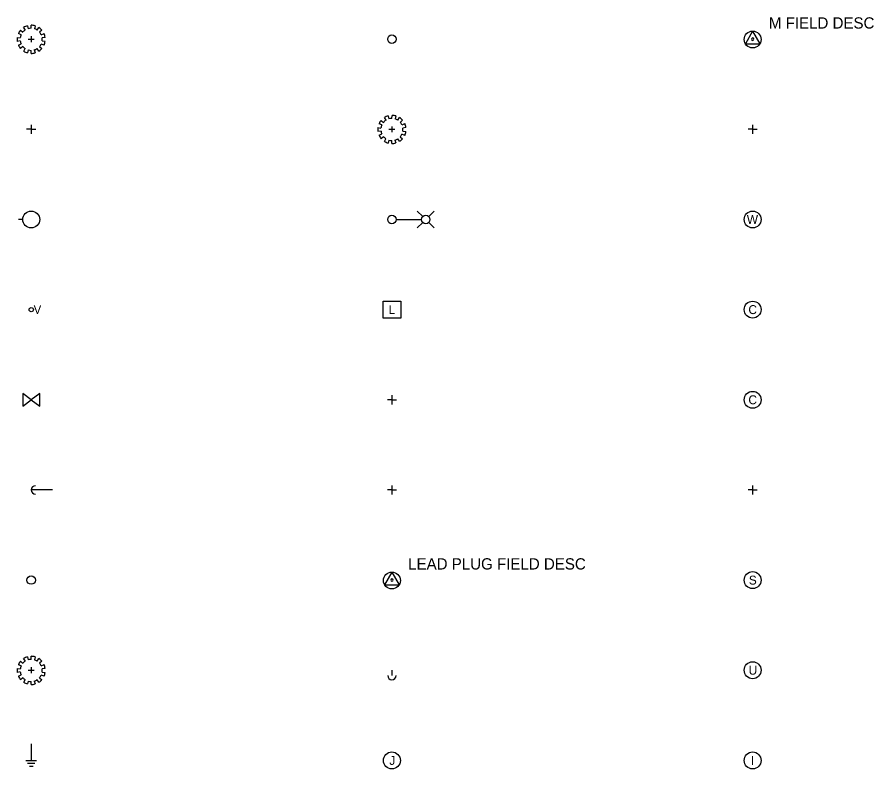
# Model space of a CAD drawing. Extents: x 91 to 2906, y -24 to 912.
# Drawn here: x 892.2 to 1367.2, y 495.3 to 912.2 of the extents above; entities that cross this region are included whole.
import ezdxf

# ---------------------------------------------------------------- set-up
doc = ezdxf.new("R2010")
doc.units = 0
for name, color, linetype in [('V-AFLD-DEVC', 7, 'Continuous'), ('V-COMM-MHOL', 7, 'Continuous'), ('V-FUEL-DEVC', 7, 'Continuous'), ('V-FUEL-VALT', 7, 'Continuous'), ('V-HTCW-JBOX', 7, 'Continuous'), ('V-INDW-JBOX', 7, 'Continuous'), ('V-POWR-POLE', 7, 'Continuous'), ('V-POWR-POLE-GUYS', 7, 'Continuous'), ('V-ROAD-SIGN', 7, 'Continuous'), ('V-SITE-OTLN', 7, 'Continuous'), ('V-SITE-VEGE', 7, 'Continuous'), ('V-SSWR-DEVC', 7, 'Continuous'), ('V-SSWR-JBOX', 7, 'Continuous'), ('V-SURV-DATA', 7, 'Continuous'), ('V-UTIL-DEVC', 7, 'Continuous'), ('V-UTIL-JBOX', 7, 'Continuous'), ('V-UTIL-MHOL', 7, 'Continuous'), ('V-WATR-DEVC', 7, 'Continuous'), ('V-WATR-VALT', 7, 'Continuous')]:
    doc.layers.add(name, color=color, linetype=linetype)

msp = doc.modelspace()

# ---------------------------------------------------------------- linework, layer by layer
at = {"layer": 'V-AFLD-DEVC'}
for p, q in [((900, 509.27), (900, 500)), ((896.98, 500), (903.02, 500)), ((897.98, 498.39), (902.02, 498.39)), ((898.99, 496.77), (901.01, 496.77))]:
    msp.add_line(p, q, dxfattribs=at)
at = {"layer": 'V-COMM-MHOL'}
for centre in [(1300, 750), (1300, 700)]:
    msp.add_circle(centre, 4.69, dxfattribs=at)
at = {"layer": 'V-FUEL-DEVC'}
msp.add_circle((900.02, 750), 1.17, dxfattribs=at)
at = {"layer": 'V-FUEL-VALT'}
for p, q in [((900, 700), (895.32, 703.53)), ((895.32, 703.53), (895.32, 696.47)), ((904.69, 703.52), (900, 700)), ((904.69, 696.48), (904.69, 703.52)), ((895.32, 696.47), (900, 700)), ((900, 700), (904.69, 696.48))]:
    msp.add_line(p, q, dxfattribs=at)
at = {"layer": 'V-HTCW-JBOX'}
for p, q in [((1300, 652.55), (1300, 647.46)), ((1300, 650), (1297.46, 650)), ((1300, 650), (1302.55, 650))]:
    msp.add_line(p, q, dxfattribs=at)
at = {"layer": 'V-INDW-JBOX'}
msp.add_circle((1300, 500), 4.69, dxfattribs=at)
at = {"layer": 'V-POWR-POLE'}
msp.add_circle((1100, 900), 2.34, dxfattribs=at)
at = {"layer": 'V-POWR-POLE-GUYS'}
msp.add_line((911.72, 650), (900, 650), dxfattribs=at)
msp.add_circle((900, 600), 2.34, dxfattribs=at)
msp.add_arc((902.34, 650), 2.34, 90, 270, dxfattribs=at)
at = {"layer": 'V-ROAD-SIGN'}
for p, q in [((1300, 852.55), (1300, 847.46)), ((1300, 850), (1297.46, 850)), ((1300, 850), (1302.55, 850))]:
    msp.add_line(p, q, dxfattribs=at)
at = {"layer": 'V-SITE-OTLN'}
for p, q in [((900, 852.55), (900, 847.46)), ((900, 850), (897.46, 850)), ((900, 850), (902.55, 850)), ((1117.09, 801.66), (1114.06, 804.69)), ((1120.41, 801.66), (1123.44, 804.69)), ((1102.34, 800), (1116.41, 800)), ((1117.09, 798.34), (1114.06, 795.31)), ((1120.41, 798.34), (1123.44, 795.31)), ((1100, 700), (1097.46, 700)), ((1100, 702.55), (1100, 697.46)), ((1100, 700), (1102.55, 700))]:
    msp.add_line(p, q, dxfattribs=at)
for centre in [(1100, 800), (1118.75, 800)]:
    msp.add_circle(centre, 2.34, dxfattribs=at)
at = {"layer": 'V-SITE-VEGE'}
for p, q in [((897.86, 907.43), (898.28, 905.79)), ((900.02, 906.04), (900.06, 907.73)), ((902.25, 907.41), (901.78, 905.78)), ((894.41, 902.4), (892.87, 903.08)), ((894.04, 904.97), (895.31, 903.84)), ((896.74, 905.1), (895.8, 906.51)), ((903.3, 905.08), (904.24, 906.47)), ((905.93, 905.01), (904.67, 903.9)), ((905.59, 902.46), (907.09, 903.21)), ((892.25, 900.98), (893.92, 900.7)), ((893.94, 899.06), (892.27, 898.76)), ((898.35, 900), (901.65, 900)), ((900, 901.65), (900, 898.35)), ((906.06, 899), (907.75, 898.8)), ((907.75, 901), (906.08, 900.73)), ((892.89, 896.68), (894.41, 897.43)), ((895.4, 895.89), (894.11, 894.78)), ((895.82, 893.32), (896.64, 894.78)), ((898.35, 894.02), (897.88, 892.41)), ((900.02, 892.1), (900.02, 893.79)), ((901.69, 894.04), (902.22, 892.43)), ((904.24, 893.36), (903.34, 894.78)), ((904.6, 895.87), (905.91, 894.78)), ((907.11, 896.66), (905.54, 897.3)), ((1096.74, 855.1), (1095.8, 856.51)), ((1097.86, 857.43), (1098.28, 855.79)), ((1100.02, 856.04), (1100.06, 857.73)), ((1102.25, 857.41), (1101.78, 855.78)), ((1103.3, 855.08), (1104.24, 856.47)), ((1092.25, 850.98), (1093.92, 850.7)), ((1094.41, 852.4), (1092.87, 853.08)), ((1094.04, 854.97), (1095.31, 853.84)), ((1100, 851.65), (1100, 848.35)), ((1105.93, 855.01), (1104.67, 853.9)), ((1105.59, 852.46), (1107.09, 853.21)), ((1107.75, 851), (1106.08, 850.73)), ((1093.94, 849.06), (1092.27, 848.76)), ((1092.89, 846.68), (1094.41, 847.43)), ((1095.4, 845.89), (1094.11, 844.78)), ((1098.35, 850), (1101.65, 850)), ((1104.6, 845.87), (1105.91, 844.78)), ((1107.11, 846.66), (1105.54, 847.3)), ((1106.06, 849), (1107.75, 848.8)), ((1095.82, 843.32), (1096.64, 844.78)), ((1098.35, 844.02), (1097.88, 842.41)), ((1100.02, 842.1), (1100.02, 843.79)), ((1101.69, 844.04), (1102.22, 842.43)), ((1104.24, 843.36), (1103.34, 844.78)), ((896.74, 555.1), (895.8, 556.51)), ((897.86, 557.43), (898.28, 555.79)), ((900.02, 556.04), (900.06, 557.73)), ((902.25, 557.41), (901.78, 555.78)), ((903.3, 555.08), (904.24, 556.47)), ((894.41, 552.4), (892.87, 553.08)), ((894.04, 554.97), (895.31, 553.84)), ((900, 551.65), (900, 548.35)), ((905.93, 555.01), (904.67, 553.9)), ((905.59, 552.46), (907.09, 553.21)), ((892.25, 550.98), (893.92, 550.7)), ((893.94, 549.06), (892.27, 548.76)), ((892.89, 546.68), (894.41, 547.43)), ((898.35, 550), (901.65, 550)), ((907.11, 546.66), (905.54, 547.3)), ((906.06, 549), (907.75, 548.8)), ((907.75, 551), (906.08, 550.73)), ((895.4, 545.89), (894.11, 544.78)), ((895.82, 543.32), (896.64, 544.78)), ((898.35, 544.02), (897.88, 542.41)), ((900.02, 542.1), (900.02, 543.79)), ((901.69, 544.04), (902.22, 542.43)), ((904.24, 543.36), (903.34, 544.78)), ((904.6, 545.87), (905.91, 544.78))]:
    msp.add_line(p, q, dxfattribs=at)
for centre, radius, start, end in [((900, 899.92), 7.81, 105.972, 122.5562), ((900, 899.92), 7.81, 73.2952, 89.5718), ((900, 899.92), 7.81, 139.7777, 156.0738), ((900, 899.92), 6.12, 122.254, 140.086), ((900, 899.92), 6.12, 89.9461, 106.3473), ((900, 899.92), 6.12, 57.451, 73.0843), ((900, 899.92), 7.81, 40.7122, 57.1166), ((900, 899.92), 6.12, 24.4529, 40.4774), ((900, 899.92), 7.81, 7.9671, 24.8625), ((900, 899.92), 7.81, 172.27, 188.583), ((900, 899.92), 6.12, 156.0557, 172.7558), ((900, 899.92), 6.12, 188.0619, 204.0332), ((900, 899.92), 6.12, 351.5431, 7.6203), ((900, 899.92), 7.81, 335.3123, 351.7042), ((900, 899.92), 7.81, 204.5394, 220.9852), ((900, 899.92), 6.12, 221.2062, 236.7795), ((900, 899.92), 7.81, 237.6108, 254.1981), ((900, 899.92), 6.12, 254.31, 270.043), ((900, 899.92), 6.12, 285.9559, 303.0564), ((900, 899.92), 7.81, 302.8434, 319.0222), ((900, 899.92), 6.12, 318.6432, 334.5795), ((900, 899.92), 7.81, 270.0356, 286.342), ((1100, 849.92), 6.12, 122.254, 140.086), ((1100, 849.92), 7.81, 105.972, 122.5562), ((1100, 849.92), 6.12, 89.9461, 106.3473), ((1100, 849.92), 7.81, 73.2952, 89.5718), ((1100, 849.92), 6.12, 57.451, 73.0843), ((1100, 849.92), 7.81, 40.7122, 57.1166), ((1100, 849.92), 7.81, 172.27, 188.583), ((1100, 849.92), 7.81, 139.7777, 156.0738), ((1100, 849.92), 6.12, 156.0557, 172.7558), ((1100, 849.92), 6.12, 24.4529, 40.4774), ((1100, 849.92), 6.12, 351.5431, 7.6203), ((1100, 849.92), 7.81, 7.9671, 24.8625), ((1100, 849.92), 7.81, 204.5394, 220.9852), ((1100, 849.92), 6.12, 188.0619, 204.0332), ((1100, 849.92), 6.12, 221.2062, 236.7795), ((1100, 849.92), 6.12, 318.6432, 334.5795), ((1100, 849.92), 7.81, 335.3123, 351.7042), ((1100, 849.92), 7.81, 237.6108, 254.1981), ((1100, 849.92), 6.12, 254.31, 270.043), ((1100, 849.92), 7.81, 270.0356, 286.342), ((1100, 849.92), 6.12, 285.9559, 303.0564), ((1100, 849.92), 7.81, 302.8434, 319.0222), ((900, 549.92), 7.81, 105.972, 122.5562), ((900, 549.92), 6.12, 89.9461, 106.3473), ((900, 549.92), 7.81, 73.2952, 89.5718), ((900, 549.92), 6.12, 57.451, 73.0843), ((900, 549.92), 7.81, 40.7122, 57.1166), ((900, 549.92), 7.81, 139.7777, 156.0738), ((900, 549.92), 6.12, 156.0557, 172.7558), ((900, 549.92), 6.12, 122.254, 140.086), ((900, 549.92), 6.12, 24.4529, 40.4774), ((900, 549.92), 7.81, 7.9671, 24.8625), ((900, 549.92), 7.81, 172.27, 188.583), ((900, 549.92), 7.81, 204.5394, 220.9852), ((900, 549.92), 6.12, 188.0619, 204.0332), ((900, 549.92), 6.12, 318.6432, 334.5795), ((900, 549.92), 6.12, 351.5431, 7.6203), ((900, 549.92), 7.81, 335.3123, 351.7042), ((900, 549.92), 6.12, 221.2062, 236.7795), ((900, 549.92), 7.81, 237.6108, 254.1981), ((900, 549.92), 6.12, 254.31, 270.043), ((900, 549.92), 7.81, 270.0356, 286.342), ((900, 549.92), 6.12, 285.9559, 303.0564), ((900, 549.92), 7.81, 302.8434, 319.0222)]:
    msp.add_arc(centre, radius, start, end, dxfattribs=at)
at = {"layer": 'V-SSWR-DEVC'}
msp.add_lwpolyline([(1095.09, 754.69), (1104.91, 754.69), (1104.91, 745.31), (1095.09, 745.31)], close=True, dxfattribs=at)
at = {"layer": 'V-SSWR-JBOX'}
msp.add_circle((1300, 600), 4.69, dxfattribs=at)
at = {"layer": 'V-SURV-DATA'}
for p, q in [((1300, 904.48), (1295.95, 897.46)), ((1300, 904.48), (1304.05, 897.46)), ((1295.95, 897.46), (1304.05, 897.46)), ((1100, 604.48), (1095.95, 597.46)), ((1100, 604.48), (1104.05, 597.46)), ((1095.95, 597.46), (1104.05, 597.46))]:
    msp.add_line(p, q, dxfattribs=at)
for centre in [(1300, 899.8), (1100, 599.8)]:
    msp.add_circle(centre, 4.69, dxfattribs=at)
for centre in [(1300, 900), (1100, 600)]:
    msp.add_arc(centre, 0.65, 92.2877, 90.5674, dxfattribs=at)
at = {"layer": 'V-UTIL-DEVC'}
for p, q in [((1100, 652.55), (1100, 647.46)), ((1100, 650), (1097.46, 650)), ((1100, 650), (1102.55, 650)), ((1100, 550), (1100, 547.07))]:
    msp.add_line(p, q, dxfattribs=at)
msp.add_arc((1100, 547.07), 2.34, 180, 0, dxfattribs=at)
at = {"layer": 'V-UTIL-JBOX'}
msp.add_circle((1100, 500), 4.69, dxfattribs=at)
at = {"layer": 'V-UTIL-MHOL'}
msp.add_circle((1300, 550), 4.69, dxfattribs=at)
at = {"layer": 'V-WATR-DEVC'}
msp.add_line((895.31, 800), (892.97, 800), dxfattribs=at)
msp.add_circle((900, 800), 4.69, dxfattribs=at)
at = {"layer": 'V-WATR-VALT'}
msp.add_circle((1300, 800), 4.69, dxfattribs=at)

# ---------------------------------------------------------------- texts
at = {"layer": 'V-COMM-MHOL'}
for p in [(1297.65, 747.54), (1297.65, 697.54)]:
    msp.add_text('C', height=4.92, dxfattribs=at).set_placement(p)
at = {"layer": 'V-FUEL-DEVC'}
msp.add_text('V', height=4.69, dxfattribs=at).set_placement((901.37, 747.66))
at = {"layer": 'V-INDW-JBOX'}
msp.add_text('I', height=4.92, dxfattribs=at).set_placement((1299.03, 497.54))
at = {"layer": 'V-SSWR-DEVC'}
msp.add_text('L', height=4.69, dxfattribs=at).set_placement((1098.29, 747.65))
at = {"layer": 'V-SSWR-JBOX'}
msp.add_text('S', height=4.92, dxfattribs=at).set_placement((1297.89, 597.54))
at = {"layer": 'V-SURV-DATA'}
for s, p in [('M FIELD DESC', (1309, 905.87)), ('LEAD PLUG FIELD DESC', (1109, 605.87))]:
    msp.add_text(s, height=6.252, dxfattribs=at).set_placement(p)
at = {"layer": 'V-UTIL-JBOX'}
msp.add_text('J', height=4.92, dxfattribs=at).set_placement((1098.55, 497.54))
at = {"layer": 'V-UTIL-MHOL'}
msp.add_text('U', height=4.92, dxfattribs=at).set_placement((1297.79, 547.54))
at = {"layer": 'V-WATR-VALT'}
msp.add_text('W', height=4.92, dxfattribs=at).set_placement((1296.79, 797.54))

doc.saveas('drawing.dxf')
